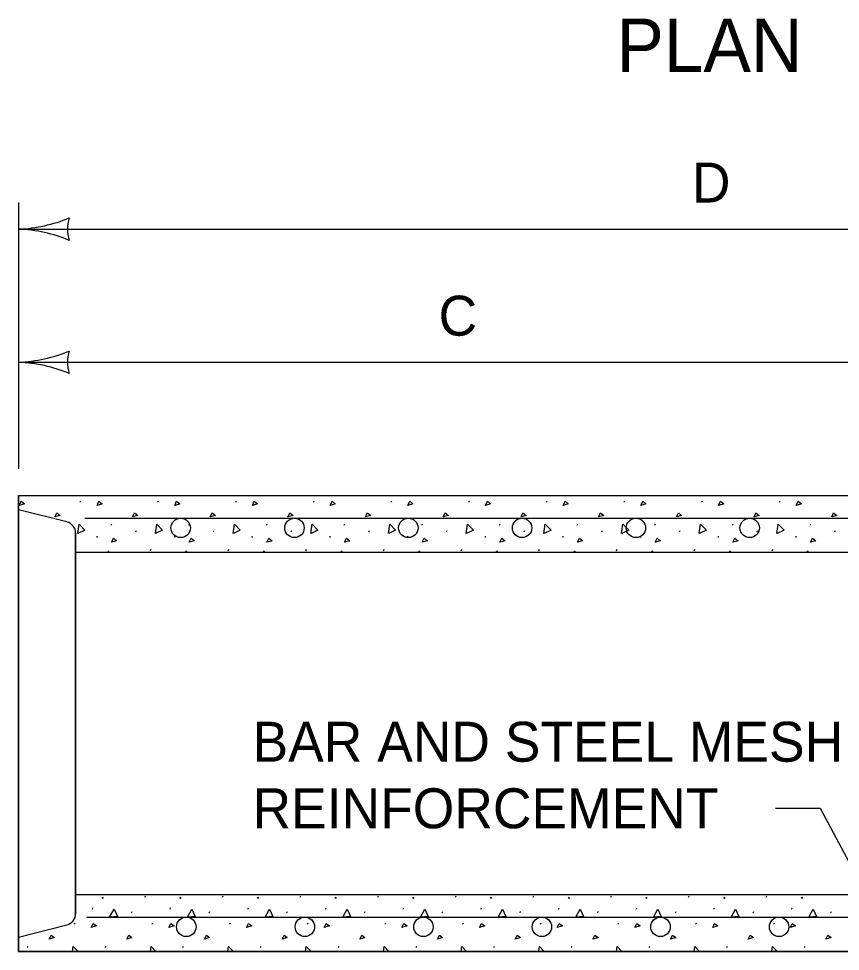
# Model space of a CAD drawing. Extents: x 49991.4 to 50022.1, y 49985 to 50011.4.
# Drawn here: x 50000.684 to 50001.918, y 49995.4 to 49996.801 of the extents above; entities that cross this region are included whole.
import ezdxf

# ---------------------------------------------------------------- set-up
doc = ezdxf.new("R2010")
doc.units = 0
for name, color, linetype in [('Level 1', 7, 'Continuous'), ('Level 2', 7, 'Continuous'), ('Level 3', 7, 'Continuous')]:
    doc.layers.add(name, color=color, linetype=linetype)

msp = doc.modelspace()

# ---------------------------------------------------------------- linework, layer by layer
at = {"layer": 'Level 1'}
for p, q in [((50000.6836, 49996.0847), (50000.6836, 49995.3998)), ((50000.6836, 49996.0847), (50001.9962, 49996.0847)), ((50000.6836, 49996.0847), (50000.6836, 49995.3998)), ((50000.6836, 49995.3998), (50000.6836, 49996.0847)), ((50000.684, 49996.0829), (50000.6847, 49996.0845)), ((50000.7757, 49996.0761), (50000.7767, 49996.0747)), ((50000.8924, 49996.0761), (50000.8934, 49996.0747)), ((50001.0091, 49996.0761), (50001.0101, 49996.0747)), ((50001.1258, 49996.0761), (50001.1268, 49996.0747)), ((50001.2425, 49996.0761), (50001.2435, 49996.0747)), ((50001.3592, 49996.0761), (50001.3602, 49996.0747)), ((50001.4759, 49996.0761), (50001.4768, 49996.0747)), ((50001.5926, 49996.0761), (50001.5935, 49996.0747)), ((50001.7092, 49996.0761), (50001.7102, 49996.0747)), ((50001.8259, 49996.0761), (50001.8269, 49996.0747)), ((50000.6836, 49996.0632), (50000.6836, 49995.4213)), ((50000.7562, 49996.0448), (50000.6836, 49996.0632)), ((50000.7562, 49996.0448), (50000.6836, 49996.0632)), ((50000.7562, 49996.0448), (50000.6836, 49996.0632)), ((50000.7562, 49996.0448), (50000.6836, 49996.0632)), ((50000.8225, 49996.0398), (50000.8235, 49996.042)), ((50000.9392, 49996.0398), (50000.9402, 49996.042)), ((50001.0559, 49996.0398), (50001.0569, 49996.042)), ((50001.1726, 49996.0398), (50001.1735, 49996.042)), ((50001.2893, 49996.0398), (50001.2902, 49996.042)), ((50001.406, 49996.0398), (50001.4069, 49996.042)), ((50001.5226, 49996.0398), (50001.5236, 49996.042)), ((50001.6393, 49996.0398), (50001.6403, 49996.042)), ((50001.756, 49996.0398), (50001.757, 49996.042)), ((50001.8727, 49996.0398), (50001.8737, 49996.042)), ((50000.7692, 49995.4563), (50000.7692, 49996.0282)), ((50000.7692, 49996.0282), (50000.7692, 49995.4854)), ((50000.8008, 49996.0237), (50000.801, 49996.0215)), ((50000.8595, 49996.0299), (50000.8605, 49996.032)), ((50000.9175, 49996.0237), (50000.9177, 49996.0215)), ((50000.9762, 49996.0299), (50000.9772, 49996.032)), ((50001.0341, 49996.0237), (50001.0344, 49996.0215)), ((50001.0929, 49996.0299), (50001.0939, 49996.032)), ((50001.1508, 49996.0237), (50001.1511, 49996.0215)), ((50001.2096, 49996.0299), (50001.2106, 49996.032)), ((50001.2675, 49996.0237), (50001.2678, 49996.0215)), ((50001.3263, 49996.0299), (50001.3273, 49996.032)), ((50001.3842, 49996.0237), (50001.3845, 49996.0215)), ((50001.443, 49996.0299), (50001.444, 49996.032)), ((50001.5009, 49996.0237), (50001.5011, 49996.0215)), ((50001.5597, 49996.0299), (50001.5606, 49996.032)), ((50001.6176, 49996.0237), (50001.6178, 49996.0215)), ((50001.6764, 49996.0299), (50001.6773, 49996.032)), ((50001.7343, 49996.0237), (50001.7345, 49996.0215)), ((50001.7931, 49996.0299), (50001.794, 49996.032)), ((50001.851, 49996.0237), (50001.8512, 49996.0215)), ((50001.9097, 49996.0299), (50001.9107, 49996.032)), ((50000.7692, 49995.999), (50000.7692, 49995.4563)), ((50002.0087, 49995.999), (50000.7692, 49995.999)), ((50000.8174, 49996.0016), (50000.8184, 49996.0001)), ((50000.8184, 49996.001), (50000.8193, 49995.9996)), ((50000.8817, 49996.0016), (50000.8827, 49996.0038)), ((50000.9341, 49996.0016), (50000.9351, 49996.0001)), ((50000.9351, 49996.001), (50000.936, 49995.9996)), ((50000.9984, 49996.0016), (50000.9994, 49996.0038)), ((50001.0508, 49996.0016), (50001.0517, 49996.0001)), ((50001.0517, 49996.001), (50001.0527, 49995.9996)), ((50001.1151, 49996.0016), (50001.1161, 49996.0038)), ((50001.1675, 49996.0016), (50001.1684, 49996.0001)), ((50001.1684, 49996.001), (50001.1694, 49995.9996)), ((50001.2318, 49996.0016), (50001.2327, 49996.0038)), ((50001.2841, 49996.0016), (50001.2851, 49996.0001)), ((50001.2851, 49996.001), (50001.2861, 49995.9996)), ((50001.3485, 49996.0016), (50001.3494, 49996.0038)), ((50001.4008, 49996.0016), (50001.4018, 49996.0001)), ((50001.4018, 49996.001), (50001.4028, 49995.9996)), ((50001.4651, 49996.0016), (50001.4661, 49996.0038)), ((50001.5175, 49996.0016), (50001.5185, 49996.0001)), ((50001.5185, 49996.001), (50001.5195, 49995.9996)), ((50001.5818, 49996.0016), (50001.5828, 49996.0038)), ((50001.6342, 49996.0016), (50001.6352, 49996.0001)), ((50001.6352, 49996.001), (50001.6362, 49995.9996)), ((50001.6985, 49996.0016), (50001.6995, 49996.0038)), ((50001.7509, 49996.0016), (50001.7519, 49996.0001)), ((50001.7519, 49996.001), (50001.7529, 49995.9996)), ((50001.8152, 49996.0016), (50001.8162, 49996.0038)), ((50001.8676, 49996.0016), (50001.8686, 49996.0001)), ((50001.8686, 49996.001), (50001.8695, 49995.9996)), ((50000.7692, 49995.4854), (50000.7692, 49995.4563)), ((50000.7692, 49995.4563), (50000.7692, 49995.4854)), ((50000.7692, 49995.4854), (50002.7668, 49995.4854)), ((50000.7692, 49995.4563), (50000.7692, 49995.4854)), ((50000.8086, 49995.4812), (50000.8096, 49995.4797)), ((50000.8096, 49995.4806), (50000.8106, 49995.4792)), ((50000.873, 49995.4812), (50000.8739, 49995.4834)), ((50000.9253, 49995.4812), (50000.9263, 49995.4797)), ((50000.9263, 49995.4806), (50000.9273, 49995.4792)), ((50000.9896, 49995.4812), (50000.9906, 49995.4834)), ((50001.042, 49995.4812), (50001.043, 49995.4797)), ((50001.043, 49995.4806), (50001.044, 49995.4792)), ((50001.1063, 49995.4812), (50001.1073, 49995.4834)), ((50001.1587, 49995.4812), (50001.1597, 49995.4797)), ((50001.1597, 49995.4806), (50001.1607, 49995.4792)), ((50001.223, 49995.4812), (50001.224, 49995.4834)), ((50001.2754, 49995.4812), (50001.2764, 49995.4797)), ((50001.2764, 49995.4806), (50001.2773, 49995.4792)), ((50001.3397, 49995.4812), (50001.3407, 49995.4834)), ((50001.3921, 49995.4812), (50001.3931, 49995.4797)), ((50001.3931, 49995.4806), (50001.394, 49995.4792)), ((50001.4564, 49995.4812), (50001.4574, 49995.4834)), ((50001.5088, 49995.4812), (50001.5098, 49995.4797)), ((50001.5098, 49995.4806), (50001.5107, 49995.4792)), ((50001.5731, 49995.4812), (50001.5741, 49995.4834)), ((50001.6255, 49995.4812), (50001.6264, 49995.4797)), ((50001.6264, 49995.4806), (50001.6274, 49995.4792)), ((50001.6898, 49995.4812), (50001.6908, 49995.4834)), ((50001.7422, 49995.4812), (50001.7431, 49995.4797)), ((50001.7431, 49995.4806), (50001.7441, 49995.4792)), ((50001.8065, 49995.4812), (50001.8074, 49995.4834)), ((50001.8588, 49995.4812), (50001.8598, 49995.4797)), ((50001.8598, 49995.4806), (50001.8608, 49995.4792)), ((50000.7943, 49995.4631), (50000.7952, 49995.4653)), ((50000.8532, 49995.4575), (50000.8542, 49995.4597)), ((50000.911, 49995.4631), (50000.9119, 49995.4653)), ((50000.9699, 49995.4575), (50000.9709, 49995.4597)), ((50001.0276, 49995.4631), (50001.0286, 49995.4653)), ((50001.0866, 49995.4575), (50001.0876, 49995.4597)), ((50001.1443, 49995.4631), (50001.1453, 49995.4653)), ((50001.2033, 49995.4575), (50001.2043, 49995.4597)), ((50001.261, 49995.4631), (50001.262, 49995.4653)), ((50001.32, 49995.4575), (50001.321, 49995.4597)), ((50001.3777, 49995.4631), (50001.3787, 49995.4653)), ((50001.4367, 49995.4575), (50001.4376, 49995.4597)), ((50001.4944, 49995.4631), (50001.4954, 49995.4653)), ((50001.5534, 49995.4575), (50001.5543, 49995.4597)), ((50001.6111, 49995.4631), (50001.6121, 49995.4653)), ((50001.67, 49995.4575), (50001.671, 49995.4597)), ((50001.7278, 49995.4631), (50001.7288, 49995.4653)), ((50001.7867, 49995.4575), (50001.7877, 49995.4597)), ((50001.8445, 49995.4631), (50001.8454, 49995.4653)), ((50001.9034, 49995.4575), (50001.9044, 49995.4597)), ((50000.6836, 49995.4213), (50000.7562, 49995.4397)), ((50000.767, 49995.442), (50000.768, 49995.4405)), ((50000.8837, 49995.442), (50000.8846, 49995.4405)), ((50001.0004, 49995.442), (50001.0013, 49995.4405)), ((50001.1171, 49995.442), (50001.118, 49995.4405)), ((50001.2337, 49995.442), (50001.2347, 49995.4405)), ((50001.3504, 49995.442), (50001.3514, 49995.4405)), ((50001.4671, 49995.442), (50001.4681, 49995.4405)), ((50001.5838, 49995.442), (50001.5848, 49995.4405)), ((50001.7005, 49995.442), (50001.7015, 49995.4405)), ((50001.8172, 49995.442), (50001.8182, 49995.4405)), ((50000.6836, 49995.3998), (50000.6836, 49995.4213)), ((50000.6971, 49995.4057), (50000.698, 49995.4078)), ((50000.8138, 49995.4057), (50000.8147, 49995.4078)), ((50000.9304, 49995.4057), (50000.9314, 49995.4078)), ((50001.0471, 49995.4057), (50001.0481, 49995.4078)), ((50001.1638, 49995.4057), (50001.1648, 49995.4078)), ((50001.2805, 49995.4057), (50001.2815, 49995.4078)), ((50001.3972, 49995.4057), (50001.3982, 49995.4078)), ((50001.5139, 49995.4057), (50001.5149, 49995.4078)), ((50001.6306, 49995.4057), (50001.6316, 49995.4078)), ((50001.7473, 49995.4057), (50001.7482, 49995.4078)), ((50001.864, 49995.4057), (50001.8649, 49995.4078)), ((50000.6836, 49995.3998), (50002.7668, 49995.3998)), ((50000.6836, 49995.3998), (50002.7668, 49995.3998)), ((50002.7668, 49995.3998), (50000.6836, 49995.3998)), ((50002.7668, 49995.3998), (50000.6836, 49995.3998)), ((50002.7668, 49995.3998), (50000.6836, 49995.3998)), ((50002.7668, 49995.3998), (50000.6836, 49995.3998))]:
    msp.add_line(p, q, dxfattribs=at)
for points in [[(50000.6846, 49996.0698), (50000.6875, 49996.0759), (50000.6924, 49996.0722), (50000.6846, 49996.0698)], [(50000.8013, 49996.0698), (50000.8042, 49996.0759), (50000.8091, 49996.0722), (50000.8013, 49996.0698)], [(50000.918, 49996.0698), (50000.9209, 49996.0759), (50000.9258, 49996.0722), (50000.918, 49996.0698)], [(50001.0347, 49996.0698), (50001.0376, 49996.0759), (50001.0425, 49996.0722), (50001.0347, 49996.0698)], [(50001.1514, 49996.0698), (50001.1543, 49996.0759), (50001.1592, 49996.0722), (50001.1514, 49996.0698)], [(50001.2681, 49996.0698), (50001.271, 49996.0759), (50001.2759, 49996.0722), (50001.2681, 49996.0698)], [(50001.3848, 49996.0698), (50001.3877, 49996.0759), (50001.3926, 49996.0722), (50001.3848, 49996.0698)], [(50001.5014, 49996.0698), (50001.5044, 49996.0759), (50001.5092, 49996.0722), (50001.5014, 49996.0698)], [(50001.6181, 49996.0698), (50001.6211, 49996.0759), (50001.6259, 49996.0722), (50001.6181, 49996.0698)], [(50001.7348, 49996.0698), (50001.7377, 49996.0759), (50001.7426, 49996.0722), (50001.7348, 49996.0698)], [(50001.8515, 49996.0698), (50001.8544, 49996.0759), (50001.8593, 49996.0722), (50001.8515, 49996.0698)], [(50000.738, 49996.0524), (50000.7409, 49996.0585), (50000.7458, 49996.0548), (50000.738, 49996.0524)], [(50000.7828, 49996.0504), (50001.9796, 49996.0504)], [(50000.8547, 49996.0524), (50000.8576, 49996.0585), (50000.8625, 49996.0548), (50000.8547, 49996.0524)], [(50000.9714, 49996.0524), (50000.9743, 49996.0585), (50000.9792, 49996.0548), (50000.9714, 49996.0524)], [(50001.0881, 49996.0524), (50001.091, 49996.0585), (50001.0959, 49996.0548), (50001.0881, 49996.0524)], [(50001.2048, 49996.0524), (50001.2077, 49996.0585), (50001.2126, 49996.0548), (50001.2048, 49996.0524)], [(50001.3215, 49996.0524), (50001.3244, 49996.0585), (50001.3293, 49996.0548), (50001.3215, 49996.0524)], [(50001.4382, 49996.0524), (50001.4411, 49996.0585), (50001.446, 49996.0548), (50001.4382, 49996.0524)], [(50001.5548, 49996.0524), (50001.5578, 49996.0585), (50001.5626, 49996.0548), (50001.5548, 49996.0524)], [(50001.6715, 49996.0524), (50001.6745, 49996.0585), (50001.6793, 49996.0548), (50001.6715, 49996.0524)], [(50001.7882, 49996.0524), (50001.7911, 49996.0585), (50001.796, 49996.0548), (50001.7882, 49996.0524)], [(50001.9049, 49996.0524), (50001.9078, 49996.0585), (50001.9127, 49996.0548), (50001.9049, 49996.0524)], [(50000.7725, 49996.0273), (50000.7744, 49996.0413), (50000.7831, 49996.0323), (50000.7727, 49996.0274)], [(50000.8892, 49996.0273), (50000.8911, 49996.0413), (50000.8998, 49996.0323), (50000.8894, 49996.0274)], [(50001.0059, 49996.0273), (50001.0078, 49996.0413), (50001.0165, 49996.0323), (50001.0061, 49996.0274)], [(50001.1225, 49996.0273), (50001.1245, 49996.0413), (50001.1332, 49996.0323), (50001.1228, 49996.0274)], [(50001.2392, 49996.0273), (50001.2412, 49996.0413), (50001.2499, 49996.0323), (50001.2395, 49996.0274)], [(50001.3559, 49996.0273), (50001.3579, 49996.0413), (50001.3666, 49996.0323), (50001.3562, 49996.0274)], [(50001.4726, 49996.0273), (50001.4745, 49996.0413), (50001.4833, 49996.0323), (50001.4728, 49996.0274)], [(50001.5893, 49996.0273), (50001.5912, 49996.0413), (50001.6, 49996.0323), (50001.5895, 49996.0274)], [(50001.706, 49996.0273), (50001.7079, 49996.0413), (50001.7167, 49996.0323), (50001.7062, 49996.0274)], [(50001.8227, 49996.0273), (50001.8246, 49996.0413), (50001.8333, 49996.0323), (50001.8229, 49996.0274)], [(50000.823, 49996.0143), (50000.8259, 49996.0204), (50000.8308, 49996.0167), (50000.823, 49996.0143)], [(50000.9397, 49996.0143), (50000.9426, 49996.0204), (50000.9475, 49996.0167), (50000.9397, 49996.0143)], [(50001.0564, 49996.0143), (50001.0593, 49996.0204), (50001.0642, 49996.0167), (50001.0564, 49996.0143)], [(50001.1731, 49996.0143), (50001.176, 49996.0204), (50001.1809, 49996.0167), (50001.1731, 49996.0143)], [(50001.2898, 49996.0143), (50001.2927, 49996.0204), (50001.2975, 49996.0167), (50001.2898, 49996.0143)], [(50001.4064, 49996.0143), (50001.4094, 49996.0204), (50001.4142, 49996.0167), (50001.4064, 49996.0143)], [(50001.5231, 49996.0143), (50001.5261, 49996.0204), (50001.5309, 49996.0167), (50001.5231, 49996.0143)], [(50001.6398, 49996.0143), (50001.6427, 49996.0204), (50001.6476, 49996.0167), (50001.6398, 49996.0143)], [(50001.7565, 49996.0143), (50001.7594, 49996.0204), (50001.7643, 49996.0167), (50001.7565, 49996.0143)], [(50001.8732, 49996.0143), (50001.8761, 49996.0204), (50001.881, 49996.0167), (50001.8732, 49996.0143)], [(50000.8203, 49995.451), (50000.8269, 49995.4634), (50000.832, 49995.4519), (50000.8206, 49995.451)], [(50000.937, 49995.451), (50000.9436, 49995.4634), (50000.9487, 49995.4519), (50000.9373, 49995.451)], [(50001.0537, 49995.451), (50001.0603, 49995.4634), (50001.0654, 49995.4519), (50001.054, 49995.451)], [(50001.1704, 49995.451), (50001.177, 49995.4634), (50001.1821, 49995.4519), (50001.1706, 49995.451)], [(50001.2871, 49995.451), (50001.2937, 49995.4634), (50001.2988, 49995.4519), (50001.2873, 49995.451)], [(50001.4038, 49995.451), (50001.4104, 49995.4634), (50001.4155, 49995.4519), (50001.404, 49995.451)], [(50001.5205, 49995.451), (50001.5271, 49995.4634), (50001.5322, 49995.4519), (50001.5207, 49995.451)], [(50001.6372, 49995.451), (50001.6437, 49995.4634), (50001.6489, 49995.4519), (50001.6374, 49995.451)], [(50001.7539, 49995.451), (50001.7604, 49995.4634), (50001.7655, 49995.4519), (50001.7541, 49995.451)], [(50001.8705, 49995.451), (50001.8771, 49995.4634), (50001.8822, 49995.4519), (50001.8708, 49995.451)], [(50000.7853, 49995.4512), (50002.7442, 49995.4512)], [(50000.7926, 49995.4356), (50000.7955, 49995.4417), (50000.8004, 49995.4381), (50000.7926, 49995.4356)], [(50000.9093, 49995.4356), (50000.9122, 49995.4417), (50000.917, 49995.4381), (50000.9093, 49995.4356)], [(50001.0259, 49995.4356), (50001.0289, 49995.4417), (50001.0337, 49995.4381), (50001.0259, 49995.4356)], [(50001.1426, 49995.4356), (50001.1456, 49995.4417), (50001.1504, 49995.4381), (50001.1426, 49995.4356)], [(50001.2593, 49995.4356), (50001.2622, 49995.4417), (50001.2671, 49995.4381), (50001.2593, 49995.4356)], [(50001.376, 49995.4356), (50001.3789, 49995.4417), (50001.3838, 49995.4381), (50001.376, 49995.4356)], [(50001.4927, 49995.4356), (50001.4956, 49995.4417), (50001.5005, 49995.4381), (50001.4927, 49995.4356)], [(50001.6094, 49995.4356), (50001.6123, 49995.4417), (50001.6172, 49995.4381), (50001.6094, 49995.4356)], [(50001.7261, 49995.4356), (50001.729, 49995.4417), (50001.7339, 49995.4381), (50001.7261, 49995.4356)], [(50001.8428, 49995.4356), (50001.8457, 49995.4417), (50001.8506, 49995.4381), (50001.8428, 49995.4356)], [(50000.7293, 49995.4182), (50000.7322, 49995.4243), (50000.7371, 49995.4206), (50000.7293, 49995.4182)], [(50000.846, 49995.4182), (50000.8489, 49995.4243), (50000.8538, 49995.4206), (50000.846, 49995.4182)], [(50000.9627, 49995.4182), (50000.9656, 49995.4243), (50000.9704, 49995.4206), (50000.9627, 49995.4182)], [(50001.0793, 49995.4182), (50001.0823, 49995.4243), (50001.0871, 49995.4206), (50001.0793, 49995.4182)], [(50001.196, 49995.4182), (50001.199, 49995.4243), (50001.2038, 49995.4206), (50001.196, 49995.4182)], [(50001.3127, 49995.4182), (50001.3156, 49995.4243), (50001.3205, 49995.4206), (50001.3127, 49995.4182)], [(50001.4294, 49995.4182), (50001.4323, 49995.4243), (50001.4372, 49995.4206), (50001.4294, 49995.4182)], [(50001.5461, 49995.4182), (50001.549, 49995.4243), (50001.5539, 49995.4206), (50001.5461, 49995.4182)], [(50001.6628, 49995.4182), (50001.6657, 49995.4243), (50001.6706, 49995.4206), (50001.6628, 49995.4182)], [(50001.7795, 49995.4182), (50001.7824, 49995.4243), (50001.7873, 49995.4206), (50001.7795, 49995.4182)], [(50001.8962, 49995.4182), (50001.8991, 49995.4243), (50001.904, 49995.4206), (50001.8962, 49995.4182)], [(50000.7647, 49995.3998), (50000.7657, 49995.4071), (50000.7728, 49995.3998)], [(50000.8814, 49995.3998), (50000.8824, 49995.4071), (50000.8895, 49995.3998)], [(50000.998, 49995.3998), (50000.999, 49995.4071), (50001.0061, 49995.3998)], [(50001.1147, 49995.3998), (50001.1157, 49995.4071), (50001.1228, 49995.3998)], [(50001.2314, 49995.3998), (50001.2324, 49995.4071), (50001.2395, 49995.3998)], [(50001.3481, 49995.3998), (50001.3491, 49995.4071), (50001.3562, 49995.3998)], [(50001.4648, 49995.3998), (50001.4658, 49995.4071), (50001.4729, 49995.3998)], [(50001.5815, 49995.3998), (50001.5825, 49995.4071), (50001.5896, 49995.3998)], [(50001.6982, 49995.3998), (50001.6992, 49995.4071), (50001.7063, 49995.3998)], [(50001.8149, 49995.3998), (50001.8159, 49995.4071), (50001.823, 49995.3998)]]:
    msp.add_lwpolyline(points, dxfattribs=at)
for centre in [(50000.927, 49996.0359), (50001.0979, 49996.0359), (50001.2689, 49996.0359), (50001.4398, 49996.0359), (50001.6108, 49996.0359), (50001.7817, 49996.0359), (50000.9354, 49995.4366), (50001.1135, 49995.4366), (50001.2916, 49995.4366), (50001.4696, 49995.4366), (50001.6477, 49995.4366), (50001.8258, 49995.4366)]:
    msp.add_circle(centre, 0.0146, dxfattribs=at)
for centre, start, end in [((50000.7521, 49996.0282), 0, 75.8703), ((50000.7521, 49995.4563), 284.1107, 0)]:
    msp.add_arc(centre, 0.0171, start, end, dxfattribs=at)
at = {"layer": 'Level 3'}
for p, q in [((50000.6836, 49996.5247), (50000.6836, 49996.1247)), ((50000.6836, 49996.4847), (50002.7668, 49996.4847)), ((50000.6836, 49996.2847), (50001.9962, 49996.2847)), ((50001.8207, 49995.6147), (50001.8874, 49995.6147)), ((50001.8874, 49995.6147), (50001.9727, 49995.4548))]:
    msp.add_line(p, q, dxfattribs=at)
for centre, radius, start, end in [((50000.6721, 49996.7174), 0.233, 272.8273, 292.0772), ((50000.8118, 49996.4847), 0.0548, 162.1388, 197.8612), ((50000.6744, 49996.2626), 0.2223, 67.456, 87.6395), ((50000.6721, 49996.5174), 0.233, 272.8273, 292.0772), ((50000.8118, 49996.2847), 0.0548, 162.1388, 197.8612), ((50000.6744, 49996.0626), 0.2223, 67.456, 87.6395)]:
    msp.add_arc(centre, radius, start, end, dxfattribs=at)

# ---------------------------------------------------------------- texts
at = {"layer": 'Level 2'}
for s, height, p in [('PLAN', 0.08, (50001.5814, 49996.721)), ('D', 0.06, (50001.6949, 49996.5247)), ('C', 0.06, (50001.3144, 49996.3247)), ('BAR AND STEEL MESH', 0.06, (50001.0349, 49995.6847)), ('REINFORCEMENT', 0.06, (50001.0349, 49995.5847))]:
    msp.add_text(s, height=height, dxfattribs=at).set_placement(p)

doc.saveas('drawing.dxf')
